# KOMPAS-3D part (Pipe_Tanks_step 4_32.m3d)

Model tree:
1. X Axis
2. Y Axis
3. Z Axis  (labels: Valve Dy 50; Pipe Dn 20)
     Òîëùèíà ñòåíêè 1 = 1

Referenced files in C:\Documents and Settings\kashirsky\Мои документы\Camtasia Studio\Pipelines3D\Tanks\: Tanks_step 4.a3d
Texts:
  Pipe Dn 20
  Steel ASTM A295
  Three Point Plane
  Plane at Angle
  Line and Point Plane
  Axis through Two Vertices
  Axis of Feature
  Axis of Conical Surface
  Axis through Edge
  Trim by Surface
  Trim by Sketch
  Feature with No History
  Intersection Axis of Two Planes
  Two Line Plane
  Line and Face Plane
  Bend by line
  Hole in sheet body
  Cut in sheet body
  Point in CM
  Linear Dimension from Line to Point
  Surface Finish Symbol
  Geometric Tolerance Symbol
  Leader #1
  Leader #2
  Leader #3
  Shape Deviations and Datum
  Node point number
  Mark of coordination axis
  Node point designation
  Mark/Reference designation with leader
  Mark/reference designation on line
  Mark/Reference designation without leader
  Valve Dy 50
  Plane of section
